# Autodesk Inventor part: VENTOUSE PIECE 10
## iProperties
Created: 2004-11
Part Number: VENTOUSE PIECE 10
Document SubType Name: Modeling
Designer: Bruno
Manufacturer: Standard
Standards Organization: Custom
Author: Bruno
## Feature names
1. Base1
